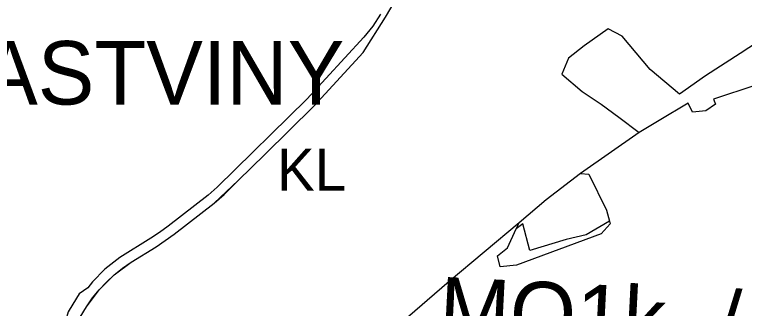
# Model space of a CAD drawing. Extents: x -706771 to -698463, y -971709 to -967107.
# Drawn here: x -701207 to -700517, y -969892 to -969614 of the extents above; entities that cross this region are included whole.
import ezdxf

# ---------------------------------------------------------------- set-up
doc = ezdxf.new("R2010")
doc.units = 0
for name, color, linetype in [('_KRAJINNY OKRSEK_popis', 7, 'Continuous'), ('KN_Hranice_parcel', 7, 'Continuous'), ('Komunikace mistni obsluzne popis N', 7, 'Continuous'), ('Prvky nelesní zeleně_dominantní aleje', 7, 'Continuous')]:
    doc.layers.add(name, color=color, linetype=linetype)

msp = doc.modelspace()

# ---------------------------------------------------------------- linework, layer by layer
at = {"layer": 'KN_Hranice_parcel'}
for p, q in [((-700616.13, -969725.77), (-700671.8, -969764.71)), ((-700732.41, -969817.06), (-700729.69, -969811.18))]:
    msp.add_line(p, q, dxfattribs=at)
for points in [[(-701163.1, -969921.52), (-701147.98, -969906.29), (-701138.56, -969890.62), (-701132.88, -969882.39), (-701126.59, -969874.62), (-701119.81, -969867.27), (-701112.42, -969860.53), (-701104.57, -969854.33), (-701096.36, -969848.63), (-701072.94, -969834), (-701055.66, -969821.95), (-701017.93, -969792.66), (-701008.55, -969784.46), (-700995.21, -969771.35), (-700970.21, -969746.77), (-700923.77, -969701.12), (-700877, -969650.11), (-700855.95, -969616.86), (-700818.64, -969553.31)], [(-700447.93, -969602.17), (-700471.58, -969615.82), (-700497.1, -969635.85), (-700520.64, -969651.32), (-700553.55, -969672.38), (-700578.01, -969689.54), (-700605.8, -969666.41), (-700632.45, -969634.67), (-700645.63, -969627.96), (-700668.35, -969643.87), (-700682.9, -969655.47), (-700689.29, -969670.89), (-700669.99, -969687.24), (-700652.07, -969699.23), (-700635.54, -969711.27), (-700616.13, -969725.77)], [(-700860.69, -969614.08), (-700868.09, -969625.28), (-700876.62, -969635.64), (-700930.48, -969694.4), (-701015.21, -969777.68), (-701023.75, -969785.15), (-701061.49, -969814.44), (-701069.6, -969820.41), (-701077.97, -969825.94), (-701107.02, -969844.08), (-701121.2, -969855), (-701133.07, -969867.23), (-701137.44, -969872.7), (-701145.45, -969878.43), (-701151.6, -969888.07), (-701156.04, -969895.5), (-701158.02, -969903.13), (-701162.59, -969910.16), (-701162.71, -969910.34)], [(-700505.91, -969681.14), (-700545.98, -969694.29), (-700544.04, -969699.26), (-700553.31, -969705.51), (-700565.88, -969706.73), (-700570, -969698.06), (-700597.45, -969714.46), (-700616.13, -969725.77)], [(-700671.8, -969764.71), (-700704.13, -969789.63), (-700729.69, -969811.18)], [(-700671.8, -969764.71), (-700663.86, -969765.3), (-700647.11, -969799.19), (-700644.22, -969809.76)], [(-700729.69, -969811.18), (-700795.98, -969866.87), (-700842.28, -969906.94)], [(-700644.22, -969809.76), (-700643.57, -969812.16), (-700652.05, -969821.7), (-700732.17, -969851.24), (-700747.72, -969852.78), (-700750.19, -969842.57), (-700740.83, -969834.94), (-700732.41, -969817.06)], [(-700644.22, -969809.76), (-700666.31, -969822.73), (-700685.11, -969827.2), (-700719.43, -969837.54), (-700726.21, -969812.14), (-700732.41, -969817.06)]]:
    msp.add_lwpolyline(points, dxfattribs=at)
at = {"layer": 'Prvky nelesní zeleně_dominantní aleje'}
msp.add_lwpolyline([(-701147.98, -969906.29), (-701138.56, -969890.62), (-701126.59, -969874.62), (-701112.42, -969860.53), (-701096.36, -969848.63), (-701072.94, -969834), (-701055.66, -969821.95), (-701017.93, -969792.66), (-700995.21, -969771.35), (-700970.21, -969746.77), (-700923.77, -969701.12), (-700877, -969650.11), (-700855.95, -969616.86), (-700818.64, -969553.31)], dxfattribs=at)

# ---------------------------------------------------------------- texts
at = {"layer": '_KRAJINNY OKRSEK_popis'}
msp.add_text('PASTVINY', height=60, dxfattribs=at).set_placement((-701291.74, -969699.43))
at = {"layer": 'Komunikace mistni obsluzne popis N'}
msp.add_text('MO1k -/4,5/30', height=60, rotation=357.09486, dxfattribs=at).set_placement((-700806.59, -969922.18))
at = {"layer": 'Prvky nelesní zeleně_dominantní aleje'}
msp.add_text('KL', height=40, dxfattribs=at).set_placement((-700958.54, -969781.04))

doc.saveas('drawing.dxf')
